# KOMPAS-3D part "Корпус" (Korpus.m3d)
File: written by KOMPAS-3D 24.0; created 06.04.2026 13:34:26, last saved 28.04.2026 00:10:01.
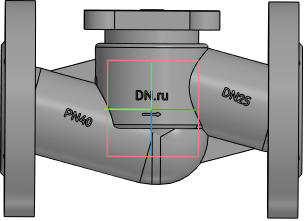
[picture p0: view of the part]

Document properties: Автор: R2D2; Полное имя файла: C:\Работа\ГОТОВЫЕ ИСХОДНИКИ\VSO2130M-F-S Клапан запорный сальниковый DN.ru Ду15-100 Ру40\исходные материалы\DN25\Korpus.m3d

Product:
- Body: Труба / Нестандартная труба / L = 108.3 мм  | qty 1  | 2 such rows
    Материал: Нестандартная труба (density 7856 kg/m3)
    Масса: 5.244691
    Раздел спецификации: Детали
    Примечание: 1,35 кг
    additional columns: Pipeline; 0.045; 0; 0; 0.002; 0.10828; true; 0.04
- Body: Тело 4  | qty 1
    Материал: Нестандартная труба (density 7856 kg/m3)
    Масса: 5.244691
- Body: Тело 5  | qty 1
    Материал: Нестандартная труба (density 7856 kg/m3)
    Масса: 5.244691
- Body: Тело 8  | qty 1
    Материал: Нестандартная труба (density 7856 kg/m3)
    Масса: 5.244691
- Body: Тело 10  | qty 1
    Материал: Нестандартная труба (density 7856 kg/m3)
    Масса: 5.244691
- Body: Тело 11  | qty 1
    Материал: Нестандартная труба (density 7856 kg/m3)
    Масса: 5.244691
- Body: Тело 12  | qty 1
    Материал: Нестандартная труба (density 7856 kg/m3)
    Масса: 5.244691
- Body: Тело 13  | qty 1
    Материал: Нестандартная труба (density 7856 kg/m3)
    Масса: 5.244691
- Part/product: Корпус
    Масса: 6.9

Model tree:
1. Труба:1  (labels: {F703FF30-5BE6-4673-A7F1-8EDA1BE1E2D1}; SHAPEOBJECT3D_ATTR_BUTT; SHAPEOBJECT3D_ATTR_VALID; SHAPEOBJECT3D_ATTR_BUTT_AREA)
     PIPE_R = 3
2. Труба:2  (labels: {F703FF30-5BE6-4673-A7F1-8EDA1BE1E2D1}; SHAPEOBJECT3D_ATTR_BUTT; SHAPEOBJECT3D_ATTR_VALID; SHAPEOBJECT3D_ATTR_BUTT_AREA)
     PIPE_R = 3
3. Колонна
4. Элемент выдавливания:1
     Смещение 1 = -1; Смещение 2 = -5
5. Скругление:17  (with: Ребро.Элемент выдавливания:1)
     Радиус = 2
6. Скругление:18  (with: Ребро.Элемент выдавливания:1)
7. Скругление:24
     Радиус = 1.5
8. Элемент выдавливания:2
     Расстояние 1 = 6
9. Эскиз:4  (with: Грань.Элемент выдавливания:1)
10. Элемент выдавливания:3
     Расстояние 1 = 7.5
11. ОТЛИВКА
12. Скругление:6  (with: Грань.Элемент выдавливания:1)
     Радиус = 2
13. Элемент выдавливания:6  (with: Грань.Элемент выдавливания:1)
     Смещение 1 = 4
14. ЛЕЙБЛ
15. Элемент выдавливания:7  (with: Грань.Элемент выдавливания:1)
     Расстояние 1 = 30.9841; Смещение 1 = 1
16. Dn
17. Pn
18. Стрелочка
19. Элемент выдавливания:10  (with: Грань.Труба:1)
     Расстояние 1 = 23.4329; Смещение 1 = 1
20. Элемент выдавливания:11  (with: Грань.Труба:2)
     Расстояние 1 = 23.3569; Смещение 1 = 1
21. Элемент выдавливания:12  (with: Грань.Элемент выдавливания:1)
     Расстояние 1 = 30.9999; Смещение 1 = 1
22. Материал
23. Элемент выдавливания:13  (with: Грань.Элемент выдавливания:1)
     Расстояние 1 = 30.3256; Смещение 1 = 0.5
24. Фланец верх  (with: Грань.Элемент выдавливания:3)
25. Элемент выдавливания:14
     Расстояние 1 = 10
26. Эскиз:18  (with: Грань.Элемент выдавливания:14)
27. Элемент выдавливания:15
     Расстояние 1 = 0.5
28. Эскиз:19  (with: Грань.Элемент выдавливания:14, Ребро.Элемент выдавливания:14)
29. Элемент выдавливания:16  (with: Грань.Элемент выдавливания:14)
     Расстояние 1 = 0.5; Расстояние 2 = 11; Смещение 2 = 1
30. Фланец
31. Элемент вращения:1
     Угол 1 = 360
32. отвертие во фланце  (with: Грань.Элемент вращения:1)  (labels: SHAPEOBJECT3D_ATTR_BUTT)
33. Элемент выдавливания:8
     Расстояние 2 = 3.29032e-05
34. Массив по концентрической сетке:2  (with: Элемент выдавливания:8, Эскиз:10, Грань.Элемент вращения:1)  (4 pattern instances)
     Шаг 2 = 360
35. Зеркальный массив:1
36. Экземпляр ( 1 )
37. Экземпляр ( 2 )  (with: Элемент вращения:1, Массив по концентрической сетке:2, Экземпляр ( 1 ), Элемент выдавливания:8)
38. Экземпляр ( 3 )  (with: Элемент выдавливания:8)
39. Экземпляр ( 4 )  (with: Элемент выдавливания:8)
40. Скругление:25  (with: Ребро.Элемент выдавливания:1)
     Радиус = 2
41. Массив по концентрической сетке:3  (with: Элемент выдавливания:16, Эскиз:19)  (labels: Клапан запорный DN.ru Ду25 Ру40)  (4 pattern instances)
     Шаг 2 = 360

Expressions: DS/2+3; DN/2; LL/2; D1/2; D2/2-8
Referenced files in C:\Работа\ГОТОВЫЕ ИСХОДНИКИ\VSO2130M-F-S Клапан запорный сальниковый DN.ru Ду15-100 Ру40\исходные материалы\DN25\: VSO2130M-F-S Клапан запорный DN.ru Ду25 Ру40.a3d
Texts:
  GOST 26.020 Pr3
  var3D
  GS-C25
  смещение колонны вниз
  LL-10
  DN+20
  DS+10
  Труба / Нестандартная труба / L = %s мм
  Ось Y.Начало координат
